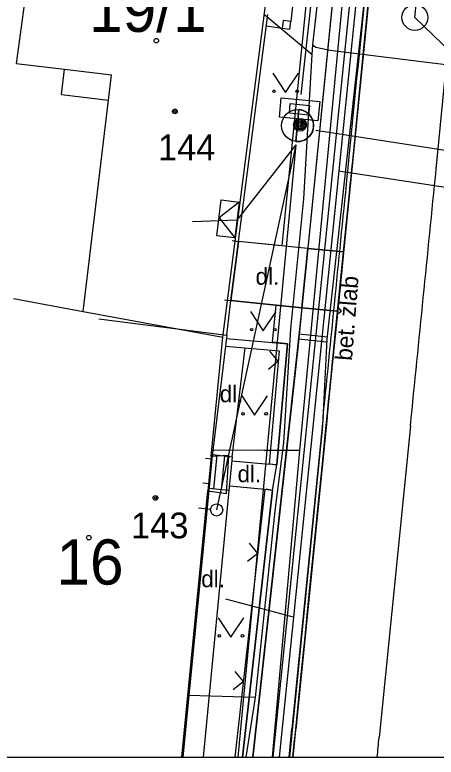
# Model space of a CAD drawing. Extents: x -643342 to -638635, y -1201752 to -1189948.
# Drawn here: x -639518.62 to -639502.29, y -1192858.61 to -1192829.85 of the extents above; entities that cross this region are included whole.
import ezdxf

# ---------------------------------------------------------------- set-up
doc = ezdxf.new("R2010")
doc.units = 0
for name, color, linetype in [('IS_EL_NN_NADZEMNÍ', 7, 'Continuous'), ('IS_EL_NN_PODZEMNÍ', 7, 'Continuous'), ('IS_PLYN_STL', 7, 'Continuous'), ('IS_TELEF_MISTNI_ZAMERENO', 7, 'Continuous'), ('IS_VODOVOD_PRIPOJKA DOMOVNÍ', 7, 'Continuous'), ('IS_VODOVOD_VAS', 7, 'Continuous'), ('K-HRANICE_KN', 7, 'Continuous'), ('K-SLUCKOVE CARY', 7, 'Continuous'), ('K-ČÍSLA_PARCEL', 7, 'Continuous'), ('N-CHODNIK', 7, 'Continuous'), ('N-KAN_DEST_SACHTY-NÁVRH', 7, 'Continuous'), ('N-KAN_DEST_TRASA-NÁVRH', 7, 'Continuous'), ('N-OBVOD STAVBY 06', 7, 'Continuous'), ('N-OSA', 7, 'Continuous'), ('N-SILNICE', 7, 'Continuous'), ('N-SRAFY_PLOCHY', 7, 'Continuous'), ('Vrstva 13', 7, 'Continuous'), ('Z-budovy', 7, 'Continuous'), ('Z-hrany_a_čáry', 7, 'Continuous'), ('Z-popisy', 7, 'Continuous'), ('Z-sloupy', 7, 'Continuous'), ('Z-vchody_vjezdy', 7, 'Continuous'), ('Z-značky', 7, 'Continuous')]:
    doc.layers.add(name, color=color, linetype=linetype)

msp = doc.modelspace()

# ---------------------------------------------------------------- linework, layer by layer
at = {"layer": 'IS_EL_NN_NADZEMNÍ'}
for p, q in [((-639503.93, -1192799.12), (-639507.53, -1192832.94)), ((-639507.73, -1192834.88), (-639509.974, -1192858.606))]:
    msp.add_line(p, q, dxfattribs=at)
for points in [[(-639507.728, -1192834.756), (-639507.611, -1192833.522)], [(-639507.611, -1192833.522), (-639507.728, -1192834.756)], [(-639509.923, -1192837.106), (-639510.705, -1192837.712), (-639510.098, -1192838.494)], [(-639511.034, -1192849.008), (-639511.502, -1192848.965)]]:
    msp.add_lwpolyline(points, dxfattribs=at)
for centre, radius in [((-639507.66, -1192834.14), 0.62), ((-639510.8, -1192849.03), 0.235)]:
    msp.add_circle(centre, radius, dxfattribs=at)
for centre, radius, start, end in [((-639507.66, -1192834.14), 0.62, 263.6713, 84.5903), ((-639507.639, -1192834.128), 0.607, 86.4158, 87.34)]:
    msp.add_arc(centre, radius, start, end, dxfattribs=at)
at = {"layer": 'IS_EL_NN_PODZEMNÍ'}
for p, q in [((-639506.96, -1192834.32), (-639485.87, -1192837.57)), ((-639507.73, -1192834.88), (-639510.8, -1192849.03)), ((-639507.73, -1192834.88), (-639510.01, -1192837.8)), ((-639510.01, -1192837.8), (-639511.74, -1192837.87))]:
    msp.add_line(p, q, dxfattribs=at)
for points in [[(-639508.296, -1192833.069), (-639506.804, -1192833.211), (-639506.874, -1192833.957), (-639508.367, -1192833.816)], [(-639507.944, -1192833.286), (-639507.202, -1192833.356), (-639507.238, -1192833.733), (-639507.98, -1192833.663)], [(-639509.923, -1192837.106), (-639510.098, -1192838.494), (-639510.793, -1192838.407), (-639510.618, -1192837.018)]]:
    msp.add_lwpolyline(points, close=True, dxfattribs=at)
at = {"layer": 'IS_PLYN_STL'}
for points in [[(-639508.636, -1192858.606), (-639507.57, -1192846.73), (-639505.85, -1192828.67), (-639505.47, -1192824.76), (-639503.15, -1192802.54), (-639502.75, -1192798.72), (-639501.54, -1192784.73), (-639501.39, -1192783.75), (-639500.989, -1192780.093)], [(-639507.57, -1192846.73), (-639508.97, -1192846.73), (-639510.97, -1192846.72)]]:
    msp.add_lwpolyline(points, dxfattribs=at)
at = {"layer": 'IS_TELEF_MISTNI_ZAMERENO'}
for p, q in [((-639506.38, -1192824.85), (-639507.08, -1192831.01)), ((-639507.11, -1192831.38), (-639508.93, -1192829.86)), ((-639507.08, -1192831.01), (-639507.11, -1192831.38)), ((-639507.08, -1192831.01), (-639506.95, -1192831.1)), ((-639506.95, -1192831.1), (-639506.4, -1192831.22)), ((-639506.4, -1192831.22), (-639497.6, -1192832.3)), ((-639506.4, -1192831.22), (-639497.6, -1192832.3)), ((-639507.11, -1192831.38), (-639507.43, -1192836.98)), ((-639507.43, -1192836.98), (-639507.94, -1192842.01)), ((-639507.43, -1192836.98), (-639507.94, -1192842.01)), ((-639507.94, -1192842.01), (-639508.21, -1192846.43)), ((-639508.21, -1192846.43), (-639508.55, -1192849.06)), ((-639508.21, -1192846.43), (-639508.55, -1192849.06)), ((-639508.55, -1192849.06), (-639509.31, -1192856.3)), ((-639509.31, -1192856.3), (-639511.88, -1192856.22)), ((-639509.31, -1192856.3), (-639509.664, -1192858.606))]:
    msp.add_line(p, q, dxfattribs=at)
at = {"layer": 'IS_VODOVOD_PRIPOJKA DOMOVNÍ'}
for points in [[(-639506.048, -1192835.895), (-639505.91, -1192835.917), (-639493.38, -1192837.836)], [(-639507.808, -1192853.178), (-639507.918, -1192853.157), (-639510.445, -1192852.48)]]:
    msp.add_lwpolyline(points, dxfattribs=at)
at = {"layer": 'IS_VODOVOD_VAS'}
for points in [[(-639513.05, -1192632.38), (-639511.6, -1192653.11), (-639509.94, -1192661.802), (-639509.17, -1192665.92), (-639508.128, -1192674.317), (-639507.037, -1192678.26), (-639504.087, -1192695.682), (-639502.448, -1192705.362), (-639494.166, -1192711.159), (-639494.54, -1192716.007), (-639495.94, -1192729.045), (-639496.55, -1192731.72), (-639496.617, -1192732.012), (-639498.895, -1192762.442), (-639502.42, -1192797.68), (-639508.622, -1192858.606)], [(-639508.361, -1192858.606), (-639507.808, -1192853.178), (-639506.048, -1192835.895), (-639505.024, -1192825.834), (-639502.574, -1192801.785), (-639502.3, -1192799.09), (-639501.659, -1192792.67), (-639499.852, -1192774.557), (-639499.821, -1192774.244), (-639499.787, -1192773.906), (-639498.645, -1192762.458), (-639497.227, -1192743.11), (-639497.188, -1192742.573), (-639497.153, -1192742.104), (-639496.521, -1192733.479), (-639496.454, -1192733.187), (-639495.873, -1192730.664), (-639495.841, -1192730.366)]]:
    msp.add_lwpolyline(points, dxfattribs=at)
at = {"layer": 'K-HRANICE_KN'}
for p, q in [((-639510.56, -1192842.33), (-639508.25, -1192824.43)), ((-639518.67, -1192840.84), (-639515.97, -1192841.34)), ((-639515.97, -1192841.34), (-639510.56, -1192842.33)), ((-639511.01, -1192846.96), (-639510.56, -1192842.33)), ((-639511.01, -1192846.96), (-639511.14, -1192848.29)), ((-639510.32, -1192846.92), (-639511.01, -1192846.96)), ((-639510.42, -1192848.39), (-639510.32, -1192846.92)), ((-639512.143, -1192858.606), (-639511.14, -1192848.29)), ((-639511.14, -1192848.29), (-639510.42, -1192848.39))]:
    msp.add_line(p, q, dxfattribs=at)
at = {"layer": 'K-SLUCKOVE CARY'}
for p, q in [((-639517.33, -1192822.78), (-639518.57, -1192831.73)), ((-639518.57, -1192831.73), (-639516.69, -1192831.96)), ((-639516.81, -1192832.93), (-639516.69, -1192831.96)), ((-639516.69, -1192831.96), (-639514.87, -1192832.18)), ((-639514.99, -1192833.15), (-639514.87, -1192832.18)), ((-639516.81, -1192832.93), (-639514.99, -1192833.15)), ((-639515.97, -1192841.34), (-639514.99, -1192833.15)), ((-639511.01, -1192846.96), (-639511.14, -1192848.29))]:
    msp.add_line(p, q, dxfattribs=at)
at = {"layer": 'K-ČÍSLA_PARCEL'}
for centre in [(-639513.134, -1192830.85), (-639515.751, -1192850.105)]:
    msp.add_circle(centre, 0.0875, dxfattribs=at)
at = {"layer": 'N-CHODNIK'}
msp.add_lwpolyline([(-639508.26, -1192838.799), (-639509.95, -1192838.63), (-639510.25, -1192840.92), (-639507.494, -1192841.198)], dxfattribs=at)
at = {"layer": 'N-KAN_DEST_SACHTY-NÁVRH'}
msp.add_circle((-639503.116, -1192829.951), 0.5, dxfattribs=at)
at = {"layer": 'N-KAN_DEST_TRASA-NÁVRH'}
msp.add_lwpolyline([(-639498.884, -1192834.039), (-639503.116, -1192829.951), (-639498.124, -1192780.201), (-639493.988, -1192740.511), (-639490.998, -1192720.223)], dxfattribs=at)
at = {"layer": 'N-OBVOD STAVBY 06'}
for points in [[(-639508.26, -1192838.799), (-639507.24, -1192828.561), (-639506.829, -1192824.445)], [(-639508.26, -1192838.799), (-639509.95, -1192838.63), (-639510.25, -1192840.92), (-639508.489, -1192841.094)], [(-639509.791, -1192858.606), (-639508.63, -1192848.26), (-639508.46, -1192847.28), (-639508.05, -1192842.59), (-639508.632, -1192842.532), (-639508.489, -1192841.094)]]:
    msp.add_lwpolyline(points, dxfattribs=at)
at = {"layer": 'N-OSA'}
msp.add_lwpolyline([(-639503.288, -1192845.773), (-639504.5, -1192857.845)], dxfattribs=at)
for centre, radius, start, end in [((-646965.2, -1192091.375), 7499.947, 354.3034191, 354.433219), ((-654428.047, -1191345.259), 14999.999, 354.2588562, 354.2970533), ((-642489.652, -1192559.732), 3000, 354.282432, 354.297053)]:
    msp.add_arc(centre, radius, start, end, dxfattribs=at)
at = {"layer": 'N-SILNICE'}
for p, q in [((-639507.265, -1192838.898), (-639505.879, -1192839.037)), ((-639507.494, -1192841.195), (-639506.109, -1192841.334)), ((-639506.671, -1192845.428), (-639507.883, -1192857.504)), ((-639506.521, -1192845.443), (-639507.734, -1192857.519))]:
    msp.add_line(p, q, dxfattribs=at)
msp.add_lwpolyline([(-639505.83, -1192824.5), (-639507.265, -1192838.898), (-639507.494, -1192841.195), (-639509.403, -1192858.606)], dxfattribs=at)
for centre, radius, start, end in [((-646965.2, -1192091.375), 7496.547, 354.3034191, 354.433219), ((-646965.2, -1192091.375), 7496.697, 354.3034191, 354.433219), ((-654422.965, -1191345.767), 14991.492, 354.2588659, 354.2970566), ((-654422.965, -1191345.767), 14991.642, 354.2588659, 354.2970566), ((-642489.652, -1192559.732), 2996.6, 354.275923, 354.297053), ((-642489.652, -1192559.732), 2996.75, 354.276211, 354.297053)]:
    msp.add_arc(centre, radius, start, end, dxfattribs=at)
at = {"layer": 'N-SRAFY_PLOCHY'}
for p, q in [((-639505.83, -1192824.5), (-639506.629, -1192832.52)), ((-639504.688, -1192827.057), (-639505.007, -1192830.286)), ((-639505.053, -1192830.753), (-639504.832, -1192828.52)), ((-639505.007, -1192830.286), (-639505.261, -1192832.845)), ((-639505.264, -1192832.88), (-639505.053, -1192830.753)), ((-639506.629, -1192832.52), (-639507.265, -1192838.898)), ((-639505.525, -1192835.5), (-639505.264, -1192832.88)), ((-639505.261, -1192832.845), (-639505.495, -1192835.197)), ((-639505.495, -1192835.197), (-639505.714, -1192837.395)), ((-639505.738, -1192837.633), (-639505.525, -1192835.5)), ((-639505.714, -1192837.395), (-639505.908, -1192839.332)), ((-639505.879, -1192839.037), (-639505.738, -1192837.633)), ((-639509.95, -1192838.63), (-639510.25, -1192840.92)), ((-639507.265, -1192838.898), (-639509.95, -1192838.63)), ((-639507.494, -1192841.198), (-639507.265, -1192838.898)), ((-639507.265, -1192838.898), (-639507.494, -1192841.195)), ((-639507.265, -1192838.898), (-639505.879, -1192839.037)), ((-639505.879, -1192839.037), (-639507.265, -1192838.898)), ((-639506.109, -1192841.334), (-639505.879, -1192839.037)), ((-639505.908, -1192839.332), (-639506.028, -1192840.529)), ((-639506.028, -1192840.529), (-639506.343, -1192843.665)), ((-639510.25, -1192840.92), (-639507.494, -1192841.198)), ((-639507.494, -1192841.196), (-639507.758, -1192843.599)), ((-639507.494, -1192841.195), (-639506.109, -1192841.334)), ((-639506.109, -1192841.334), (-639507.494, -1192841.196)), ((-639506.214, -1192842.379), (-639506.109, -1192841.334)), ((-639506.32, -1192843.444), (-639506.214, -1192842.379)), ((-639507.758, -1192843.599), (-639507.979, -1192845.619)), ((-639506.343, -1192843.665), (-639506.631, -1192846.534)), ((-639506.456, -1192844.792), (-639506.32, -1192843.444)), ((-639506.577, -1192845.998), (-639506.456, -1192844.792)), ((-639507.979, -1192845.619), (-639508.175, -1192847.407)), ((-639506.702, -1192847.244), (-639506.577, -1192845.998)), ((-639506.631, -1192846.534), (-639506.917, -1192849.384)), ((-639508.175, -1192847.407), (-639508.527, -1192850.619)), ((-639506.839, -1192848.603), (-639506.702, -1192847.244)), ((-639507.032, -1192850.532), (-639506.839, -1192848.603)), ((-639506.917, -1192849.384), (-639507.154, -1192851.745)), ((-639507.209, -1192852.288), (-639507.032, -1192850.532)), ((-639508.527, -1192850.619), (-639508.927, -1192854.262)), ((-639507.154, -1192851.745), (-639507.405, -1192854.243)), ((-639507.387, -1192854.063), (-639507.209, -1192852.288)), ((-639508.927, -1192854.262), (-639509.137, -1192856.221)), ((-639507.405, -1192854.243), (-639507.661, -1192856.789)), ((-639507.533, -1192855.517), (-639507.387, -1192854.063)), ((-639507.734, -1192857.519), (-639507.533, -1192855.517)), ((-639509.137, -1192856.221), (-639509.284, -1192857.522)), ((-639507.661, -1192856.789), (-639507.843, -1192858.606)), ((-639509.284, -1192857.522), (-639509.403, -1192858.606)), ((-639507.843, -1192858.606), (-639507.734, -1192857.519)), ((-639509.403, -1192858.606), (-639507.843, -1192858.606)), ((-639507.843, -1192858.606), (-639501.31, -1192858.606))]:
    msp.add_line(p, q, dxfattribs=at)
at = {"layer": 'Vrstva 13'}
msp.add_lwpolyline([(-639343.591, -1192858.606), (-639343.591, -1192648.606), (-639640.591, -1192648.606), (-639640.591, -1192858.606), (-639343.591, -1192858.606)], dxfattribs=at)
at = {"layer": 'Z-budovy'}
for p, q in [((-639509.95, -1192838.63), (-639508.82, -1192829.84)), ((-639510.25, -1192840.92), (-639509.95, -1192838.63)), ((-639510.41, -1192842.26), (-639510.25, -1192840.92)), ((-639515.369, -1192841.622), (-639510.41, -1192842.26)), ((-639515.369, -1192841.622), (-639510.41, -1192842.26)), ((-639510.41, -1192842.26), (-639510.98, -1192847.05)), ((-639510.98, -1192847.05), (-639511.08, -1192848.01)), ((-639511.08, -1192848.01), (-639512.109, -1192858.606))]:
    msp.add_line(p, q, dxfattribs=at)
at = {"layer": 'Z-hrany_a_čáry'}
for p, q in [((-639505.83, -1192824.5), (-639507.65, -1192842.76)), ((-639504.85, -1192827.17), (-639506.53, -1192842.42)), ((-639507.786, -1192828.916), (-639507.92, -1192830.103)), ((-639508.217, -1192830.063), (-639508.257, -1192830.36)), ((-639507.92, -1192830.103), (-639508.217, -1192830.063)), ((-639507.96, -1192830.4), (-639507.92, -1192830.103)), ((-639508.877, -1192830.28), (-639508.257, -1192830.36)), ((-639508.257, -1192830.36), (-639507.96, -1192830.4)), ((-639507.265, -1192838.898), (-639509.95, -1192838.63)), ((-639507.494, -1192841.195), (-639510.25, -1192840.92)), ((-639507.595, -1192842.208), (-639506.519, -1192842.321)), ((-639510.425, -1192842.389), (-639508.05, -1192842.59)), ((-639507.615, -1192842.406), (-639506.535, -1192842.52)), ((-639506.53, -1192842.42), (-639506.7, -1192845.77)), ((-639510.461, -1192842.687), (-639508.375, -1192842.864)), ((-639510.2, -1192846.97), (-639509.698, -1192842.752)), ((-639507.65, -1192842.76), (-639509.401, -1192858.606)), ((-639508.05, -1192842.59), (-639508.46, -1192847.28)), ((-639508.375, -1192842.864), (-639508.759, -1192847.254)), ((-639508.41, -1192843.269), (-639508.732, -1192842.885)), ((-639508.41, -1192843.269), (-639508.794, -1192843.591)), ((-639506.7, -1192845.77), (-639507.981, -1192858.606)), ((-639510.96, -1192846.88), (-639510.2, -1192846.97)), ((-639510.796, -1192846.899), (-639510.918, -1192848.222)), ((-639510.498, -1192846.935), (-639510.619, -1192848.251)), ((-639510.2, -1192846.97), (-639510.32, -1192848.28)), ((-639510.214, -1192847.121), (-639508.759, -1192847.254)), ((-639508.46, -1192847.28), (-639508.759, -1192847.254)), ((-639510.32, -1192848.28), (-639511.323, -1192858.606)), ((-639510.32, -1192848.28), (-639511.099, -1192848.204)), ((-639510.304, -1192848.101), (-639508.928, -1192848.227)), ((-639508.928, -1192848.227), (-639510.093, -1192858.606)), ((-639508.63, -1192848.26), (-639509.791, -1192858.606)), ((-639508.928, -1192848.227), (-639508.63, -1192848.26)), ((-639509.207, -1192850.711), (-639509.519, -1192850.32)), ((-639509.207, -1192850.711), (-639509.598, -1192851.024)), ((-639509.764, -1192855.68), (-639510.077, -1192855.289)), ((-639509.764, -1192855.68), (-639510.156, -1192855.993))]:
    msp.add_line(p, q, dxfattribs=at)
at = {"layer": 'Z-sloupy'}
for radius in [0.25, 0.2, 0.15, 0.1, 0.05]:
    msp.add_circle((-639507.57, -1192834.11), radius, dxfattribs=at)
at = {"layer": 'Z-vchody_vjezdy'}
for p, q in [((-639510.25, -1192840.92), (-639509.95, -1192838.63)), ((-639510.198, -1192838.598), (-639509.95, -1192838.63)), ((-639510.498, -1192840.888), (-639510.25, -1192840.92)), ((-639511.229, -1192847.024), (-639510.98, -1192847.05)), ((-639511.08, -1192848.01), (-639510.98, -1192847.05)), ((-639508.706, -1192847.237), (-639508.46, -1192847.28)), ((-639508.63, -1192848.26), (-639508.46, -1192847.28)), ((-639511.329, -1192847.984), (-639511.08, -1192848.01)), ((-639508.876, -1192848.217), (-639508.63, -1192848.26))]:
    msp.add_line(p, q, dxfattribs=at)
at = {"layer": 'Z-značky'}
for p, q in [((-639508.627, -1192832.111), (-639508.127, -1192832.861)), ((-639508.127, -1192832.861), (-639507.627, -1192832.111)), ((-639509.492, -1192841.345), (-639508.992, -1192842.095)), ((-639508.992, -1192842.095), (-639508.492, -1192841.345)), ((-639509.827, -1192844.604), (-639509.327, -1192845.354)), ((-639509.327, -1192845.354), (-639508.827, -1192844.604)), ((-639510.746, -1192853.207), (-639510.246, -1192853.957)), ((-639510.246, -1192853.957), (-639509.746, -1192853.207))]:
    msp.add_line(p, q, dxfattribs=at)
for centre, radius in [((-639508.577, -1192832.811), 0.05), ((-639507.678, -1192832.811), 0.05), ((-639512.415, -1192833.593), 0.09), ((-639512.415, -1192833.593), 0.0398), ((-639509.442, -1192842.045), 0.05), ((-639508.543, -1192842.045), 0.05), ((-639509.777, -1192845.304), 0.05), ((-639508.878, -1192845.304), 0.05), ((-639513.172, -1192848.563), 0.09), ((-639513.172, -1192848.563), 0.0398), ((-639510.696, -1192853.907), 0.05), ((-639509.797, -1192853.907), 0.05)]:
    msp.add_circle(centre, radius, dxfattribs=at)

# ---------------------------------------------------------------- texts
at = {"layer": 'K-ČÍSLA_PARCEL'}
for s, p in [('19/1', (-639515.744, -1192830.51)), ('16', (-639517.009, -1192851.921))]:
    msp.add_text(s, height=1.75, dxfattribs=at).set_placement(p)
at = {"layer": 'Z-popisy'}
for s, height, p in [('144', 1, (-639513.075, -1192835.485)), ('dl.', 0.65, (-639509.29, -1192840.308)), ('dl.', 0.65, (-639510.68, -1192844.857)), ('dl.', 0.65, (-639509.99, -1192847.955)), ('143', 1, (-639514.119, -1192850.132)), ('dl.', 0.65, (-639511.397, -1192852.022))]:
    msp.add_text(s, height=height, dxfattribs=at).set_placement(p)
msp.add_text('bet. žlab', height=0.65, rotation=85.4392, dxfattribs=at).set_placement((-639505.556, -1192843.265))

doc.saveas('drawing.dxf')
